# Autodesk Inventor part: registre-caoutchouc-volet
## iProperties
Author: chr
Created: 2001-06
Part Number: registre-caoutchouc-volet
Material: Par défaut
Document SubType Name: Modélisation
Designer: chr
Control State: 0
Master: False
Checked Out: False
PropertySet Name: Design Tracking Control
Shininess: 20.0
PropertySet Name: _Private Model Information
Length Units: 11269
Angle Units: 11286
Time Units: 11279
Mass Units: 11290
Length Display Precision: 3
Angle Display Precision: 2
Compacted: False
Density: 0.0
Volumn: 0.0
Area: 0.0
PropertySet Name: Model Information
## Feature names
1. Extrusion1
2. Extrusion2
3. Extrusion3
4. Congé1 [Fillet]
5. Congé2 [Fillet]
6. Congé3 [Fillet]
7. Extrusion4
8. Symétrie1 [Mirror]
9. Extrusion5
10. Extrusion6
11. Symétrie2 [Mirror]
12. Perçage1 [Hole]
13. Réseau rectangulaire1 [Rectangular Pattern]
